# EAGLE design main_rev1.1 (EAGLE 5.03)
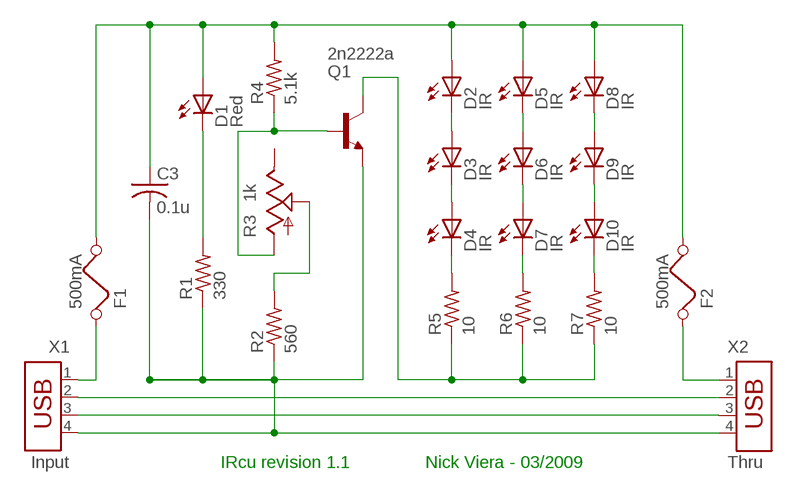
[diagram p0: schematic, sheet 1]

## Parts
C3  0.1u  C-US050-024X044  [C050-024X044]
D1  Red  LED5MM  [LED5MM]
D2  IR  LED5MM  [LED5MM]
D3  IR  LED5MM  [LED5MM]
D4  IR  LED5MM  [LED5MM]
D5  IR  LED5MM  [LED5MM]
D6  IR  LED5MM  [LED5MM]
D7  IR  LED5MM  [LED5MM]
D8  IR  LED5MM  [LED5MM]
D9  IR  LED5MM  [LED5MM]
D10  IR  LED5MM  [LED5MM]
F1  500mA  FUSE  [FUSE]
F2  500mA  FUSE  [FUSE]
Q1  2n2222a  -NPN-TO92  [TO92]
R1  330  R-US_0207/10  [0207/10]
R2  560  R-US_0207/10  [0207/10]
R3  1k  TRIM_US-B90P  [SP19L]
R4  5.1k  R-US_0207/10  [0207/10]
R5  10  R-US_0207/10  [0207/10]
R6  10  R-US_0207/10  [0207/10]
R7  10  R-US_0207/10  [0207/10]
X1  Input  USB-787616  [USB]
X2  Thru  USB-787616  [USB]

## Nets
N$1: F1.1 X1.1
N$2: D3.K(C) D4.A
N$3: D2.K(C) D3.A
N$4: D4.K(C) R5.2
N$5: D7.K(C) R6.2
N$6: D1.K(C) R1.2
N$7: C3.2 Q1.1(E) R1.1 R2.1 X1.4 X2.4
N$8: D10.K(C) R7.2
N$9: D8.K(C) D9.A
N$10: D5.K(C) D6.A
N$11: Q1.3(C) R5.1 R6.1 R7.1
N$12: D6.K(C) D7.A
N$13: Q1.2(B) R3.A R4.1
N$14: D9.K(C) D10.A
N$15: X1.2 X2.2
N$16: X1.3 X2.3
N$18: R2.2 R3.S
N$20: C3.1 D1.A D2.A D5.A D8.A F1.2 F2.2 R4.2
N$21: F2.1 X2.1
Unconnected: R3.E

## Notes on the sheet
- IRcu revision 1.1 | Nick Viera - 03/2009

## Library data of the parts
C3 = resistor:C-US: CAPACITOR, American symbol
D1-D10 = led:LED: LED
F1 F2 = special:FUSE: FUSE
Q1 = transistor-neu-to92:*-NPN-: NPN Transistror
R1 R2 R4-R7 = resistor:R-US_: RESISTOR, American symbol
R3 = pot:TRIM_US-: POTENTIOMETER
X1 X2 = con-amp:USB-787616: AMP connector

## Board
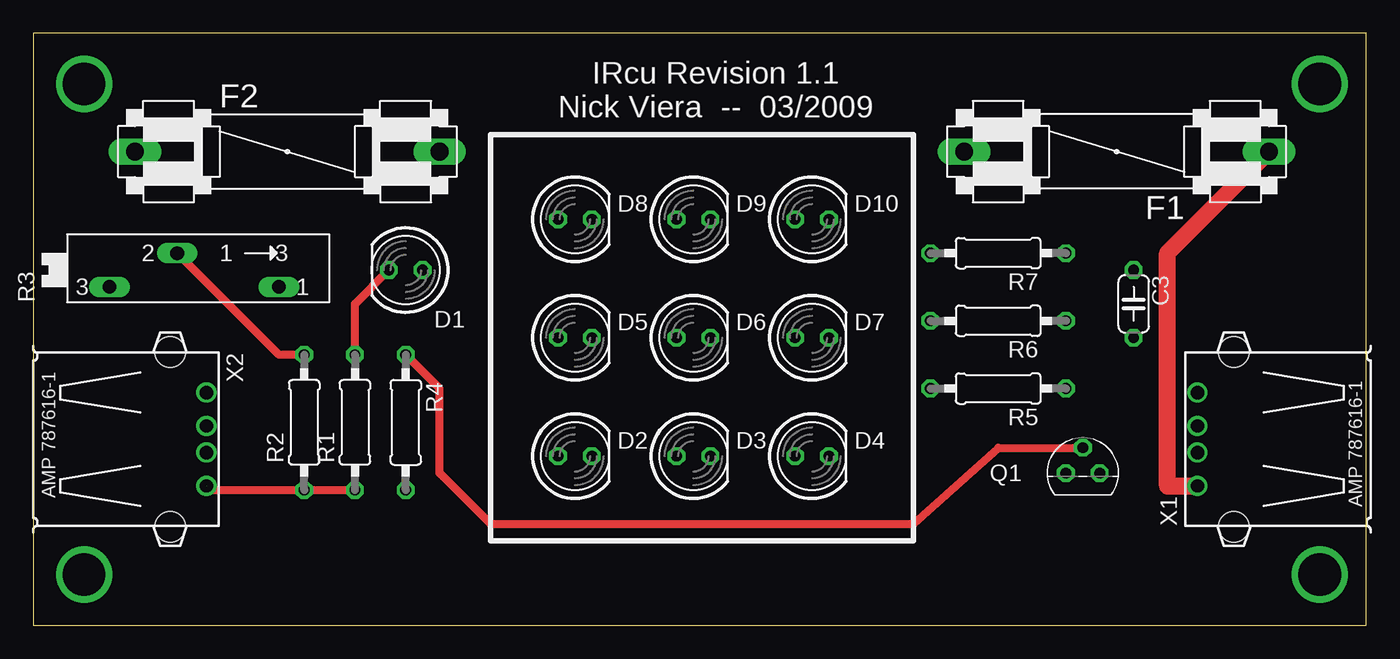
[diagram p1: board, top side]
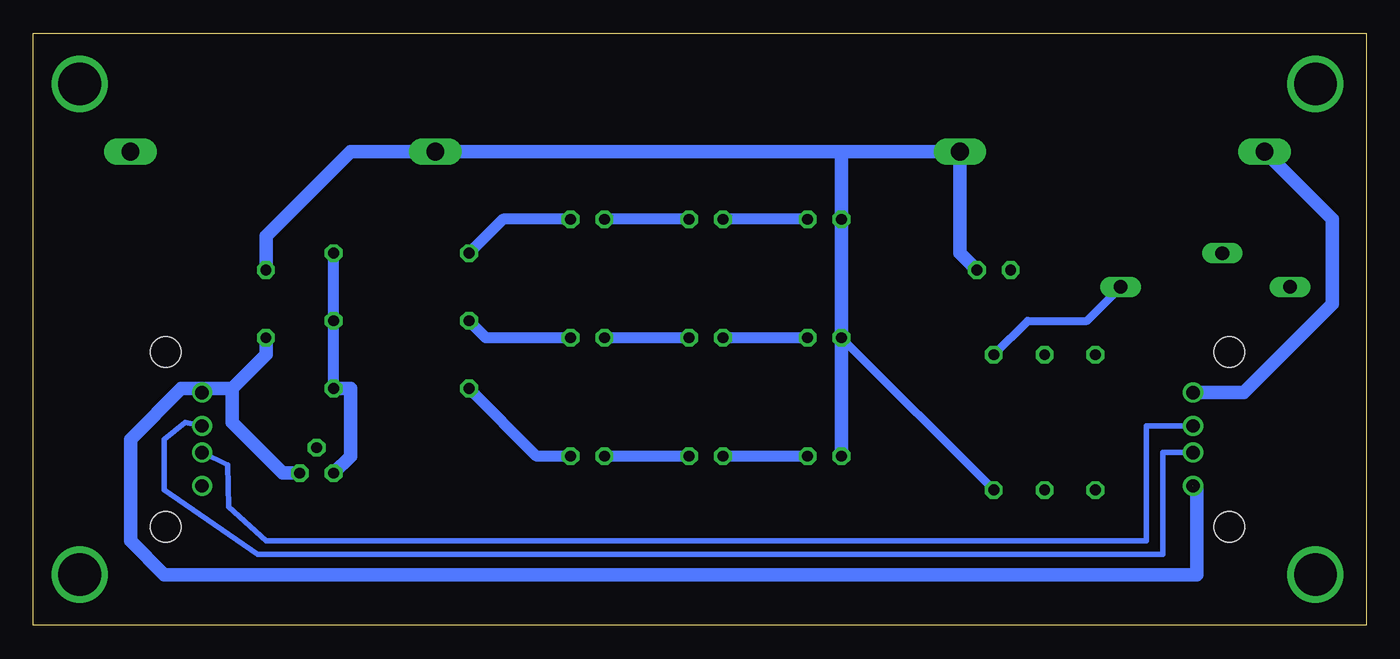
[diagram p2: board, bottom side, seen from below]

Size 100 x 44.44 mm. Coordinates in mm from the lower left corner, seen from the top.
Outline: 0,0 100,0 100,44.44 0,44.44 0,0
Copper layers (1*16): Top 0.035mm / dielectric 1.5mm / Bottom 0.035mm
Design rules "default": minimum track width 10mil, minimum drill 24mil, track to track 8mil, track to pad 8mil, pad to pad 8mil, via to via 8mil, smd to smd 8mil, copper to edge 40mil, drill to drill 8mil, minimum pad ring 10mil, minimum via ring 8mil, stop-mask expansion 4mil, vias tented up to drill 0mil, thermal gap 10mil

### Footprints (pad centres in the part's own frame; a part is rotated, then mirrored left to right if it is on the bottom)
C050-024X044 = drill 0.813 octagon: 1 -2.54,0; 2 2.54,0
LED5MM = drill 0.813 octagon: A -1.27,0; K 1.27,0
FUSE = drill 1.321 long: 1 -11.43,0; 2 11.43,0
TO92 = drill 0.813 octagon: 1 1.27,0; 2 0,1.905; 3 -1.27,0
0207/10 = drill 0.813 octagon: 1 -5.08,0; 2 5.08,0
SP19L = drill 1.016 long: A 5.715,-1.27; E -6.985,-1.27; S -1.905,1.27
USB = drill 1 round: 1 -3.5,12.99; 2 -1,12.99; 3 1,12.99; 4 3.5,12.99 | hole 2.3: -6.57,10.28; 6.57,10.28

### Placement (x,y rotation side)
C3  82.55,24.13 270 top
D1  27.94,26.67 180 top
D2  40.64,12.7 0 top
D3  49.53,12.7 0 top
D4  58.42,12.7 0 top
D5  40.64,21.59 0 top
D6  49.53,21.59 0 top
D7  58.42,21.59 0 top
D8  40.64,30.48 0 top
D9  49.53,30.48 0 top
D10  58.42,30.48 0 top
F1  81.28,35.56 180 top
F2  19.05,35.56 0 top
Q1  78.74,11.43 0 top
R1  24.13,15.24 90 top
R2  20.32,15.24 90 top
R3  12.7,26.67 0 top
R4  27.94,15.24 270 top
R5  72.39,17.78 180 top
R6  72.39,22.86 180 top
R7  72.39,27.94 180 top
X1  100.33,13.97 90 top
X2  0,13.97 270 top

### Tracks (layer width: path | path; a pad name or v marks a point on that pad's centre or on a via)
N$1
  Top 1.27: X1.1 85.09,10.47 85.09,27.94 F1.1
N$2
  Bottom 0.813: D3.K D4.A
N$3
  Bottom 0.813: D2.K D3.A
N$4
  Bottom 0.813: D4.K 62.23,12.7 R5.2
N$5
  Bottom 0.813: D7.K 66.04,21.59 R6.2
N$6
  Top 0.61: R1.2 24.13,24.13 D1.K
N$7  (1 unrouted)
  Top 0.61: R1.1 R2.1 13.3,10.16 X2.4
  Bottom 0.406: 87.34,17.78 X1.4
  Bottom 1.016: 87.34,17.78 88.9,17.78 92.71,13.97 92.71,6.35 90.17,3.81 12.7,3.81 12.7,10.47 13.01,10.47 12.7,10.16 | X1.4 87.03,17.78 85.09,17.78 | 85.09,17.78 82.55,20.32 C3.2 | Q1.1 81.28,11.43 85.09,15.24 85.09,17.78
N$8
  Bottom 0.813: D10.K 64.77,30.48 R7.2
N$9
  Bottom 0.813: D8.K D9.A
N$10
  Bottom 0.813: D5.K D6.A
N$11
  Bottom 0.813: R6.1 R5.1 R7.1
  Bottom 1.016: Q1.3 76.2,12.7 76.2,17.78 R5.1
N$12
  Bottom 0.813: D6.K D7.A
N$13
  Top 0.61: Q1.2 72.39,13.34 66.04,7.62 34.29,7.62 30.48,11.43 30.48,17.78 R4.1
  Bottom 0.61: R4.1 25.4,22.86 20.95,22.86 R3.A
N$14
  Bottom 0.813: D9.K D10.A
N$15
  Bottom 0.406: X2.2 16.51,14.97 16.51,6.35 82.55,6.35 85.34,8.89 85.44,12.06 X1.2
N$16
  Bottom 0.406: X2.3 15.24,12.97 15.24,5.33 83.19,5.33 90.17,10.16 90.17,13.97 88.61,15.24 X1.3
N$18
  Top 0.61: R2.2 18.41,20.32 R3.S
N$19  (via drill 3.2)
  other vias: 3.81,40.64
N$20
  Bottom 0.61: R4.2 D5.A
  Bottom 1.016: C3.1 82.55,29.21 76.2,35.56 F1.2 39.37,35.56 | 39.37,35.56 F2.2 30.48,27.94 D1.A | D2.A D5.A D8.A 39.37,35.56
N$21
  Bottom 1.016: X2.1 9.2,17.47 2.54,24.13 2.54,30.48 F2.1
N$22  (via drill 3.2)
  other vias: 96.52,3.81
N$23  (via drill 3.2)
  other vias: 96.52,40.64
N$24  (via drill 3.2)
  other vias: 3.81,3.81

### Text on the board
tNames: IRcu Revision 1.1 | Nick Viera -- 03/2009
